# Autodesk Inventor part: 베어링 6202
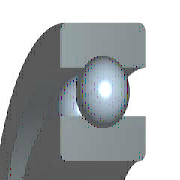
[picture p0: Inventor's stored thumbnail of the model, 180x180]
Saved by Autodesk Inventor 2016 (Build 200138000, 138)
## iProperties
IsCustomPart: 1
Created: 2015-09
Part Number: 베어링 6202
Material: 강철, 연강
Description: 깊은 그루브 볼 베어링
Document SubType Name: Modeling
Standard: KS B 2023
Designer: mduedu
Standards Organization: KS
Language: ko-KR
Size Designation: 6202 - 15 x 35 x 11
Categories: <MemberInstance><Categories><Category DisplayName="샤프트 부품" InternalName="7f7aeb1f-a693-4053-b835-cee3144e0d98" Mnemonic="SHFT"><Category DisplayName="베어링" Inter
Density: 7.86 g/cm^3
Mass: 45.8725 g
Surface Area: 51.5584 cm^2
Volume: 5.83619 cm^3
Appearance: 노란색
Author: mduedu
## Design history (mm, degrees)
sketch "스케치" dims "d0" = 5.2 (= -0.26 x WD + 0.26 x BD)
  geometry: L1 (2.9, 12.5)-(8.1, 12.5); L2 (5.5, 12.5)-(5.5, 9.9); L3 (5.5, 12.5)-(5.5, 15.1); L4 (3.568, 10.76)-(0, 10.76); L5 (0, 7.5)-(11, 7.5); L6 (3.568, 14.24)-(0, 14.24); L7 (0, 17.5)-(11, 17.5); L8 (11, 7.5)-(11, 10.76); L9 (7.432, 10.76)-(11, 10.76); L10 (7.432, 14.24)-(11, 14.24); L11 (11, 17.5)-(11, 14.24); L12 (-1.4, 0)-(8.4, 0) reference; L13 (0, -0.3)-(0, 5.3) reference
  constraints: 22 end point, 4 point on line, 2 collinear, 2 perpendicular, 2 symmetric about line, 1 midpoint, 1 parallel, 14 other
  dimensions: "d9" = 15 diameter of L5 L12 (= WD); "d11" = 35 diameter of L7 L12 (= BD); "d12" = 11 distance between parallel lines of L8 L13 (= KB); "d13" = 21.52 diameter of L9 L12 (= 0.326 x BD + 0.674 x WD)
revolve "본체" stored, may be unused: angle "d6" = 90 deg
revolve "볼" stored, may be unused: angle "d7" = 90 deg
pattern_circular "IDS_ARRAYBALL[SIMPL:T]" dims angle "d3" = 360 deg
body "Solid1"
fillet "모깎기1" dims "d1" = 0.6 (= KRS)
other parameters: "WD" = 15 [user parameter; used in 5 equation terms], "BD" = 35 [user parameter; used in 5 equation terms], "KB" = 11 [user parameter; used in 1 equation term], "KRS" = 0.6 [user parameter; used in 1 equation term], "d4" = 0, "d5" = 0, "d8" = 0, "d14" = 0, "d15" = 0, "BBA" = 0 [user parameter], "BC0" = 3750000 [user parameter], "BC" = 7800000 [user parameter], "BR" = 17.5 (= 0.5 x BD) [user parameter], "WR" = 7.5 (= 0.5 x WD) [user parameter]
